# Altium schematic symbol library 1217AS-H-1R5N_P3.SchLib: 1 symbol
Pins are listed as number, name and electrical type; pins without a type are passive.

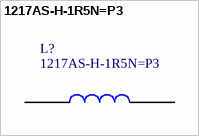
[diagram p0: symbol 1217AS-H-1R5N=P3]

## 1217AS-H-1R5N=P3
designator L?
Inductor with Inductance: 1.5uH Tol. +/-30%, Package: 3131 _8080_; MF: Murata
footprint *IND_1217AS-H-1R5N=P3
pins: 1, 2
